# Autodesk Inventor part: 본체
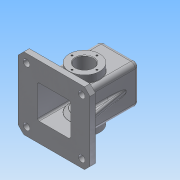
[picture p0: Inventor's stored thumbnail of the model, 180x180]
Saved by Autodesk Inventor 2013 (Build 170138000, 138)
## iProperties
Created: 2016-02
Part Number: 본체
Material: 알루미늄 6061
Document SubType Name: Modeling
Designer: Administrator
Density: 2.71 g/cm^3
Mass: 889.78 g
Surface Area: 1017.18 cm^2
Volume: 328.332 cm^3
Author: Administrator
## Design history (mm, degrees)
sketch "스케치1"
  geometry: L1 (65, 65)-(-65, 65); L2 (-65, 65)-(-65, -65); L3 (-65, -65)-(65, -65); L4 (65, -65)-(65, 65); L5 (65, 65)-(-65, -65); L6 (-65, 65)-(65, -65); 1 further point
  constraints: 12 end point, 2 midpoint, 2 parallel, 1 horizontal, 1 perpendicular
  dimensions: "d0" = 130 distance of L3.end L2.end; "d1" = 130 distance of L2.end L1.end
extrude "돌출1" new body sketch "스케치1" distance "d2" = 10; taper "d3" = 0 deg
sketch "스케치2"
  geometry: L1 (-35, -35)-(35, -35); L2 (35, -35)-(35, 35); L3 (35, 35)-(-35, 35); L4 (-35, 35)-(-35, -35); L5 (-35, -35)-(35, 35); L6 (35, -35)-(-35, 35); 1 further point
  constraints: 12 end point, 2 midpoint, 2 parallel, 1 horizontal, 1 perpendicular
  dimensions: "d4" = 70 distance of L3.end L2.end; "d5" = 70 distance of L2.end L1.end
extrude "돌출2" join sketch "스케치2" distance "d6" = 110; taper "d7" = 0 deg
sketch "스케치3"
  geometry: L1 (-35, -35)-(-35, 35) reference; L2 (-35, 35)-(35, 35) reference; L3 (35, 35)-(35, -35) reference; L4 (35, -35)-(-35, -35) reference; L5 (-65, -65)-(65, -65) reference; L6 (65, -65)-(65, 65) reference; L7 (65, 65)-(-65, 65) reference; L8 (-65, 65)-(-65, -65) reference; C1 r 20 at (0, 0); 1 further point
  constraints: 1 centre point, 1 coincident
  dimensions: "d8" = 40 diameter of C1
extrude "돌출3" join sketch "스케치3" distance "d9" = 10; taper "d10" = -10 deg
sketch "스케치4"
  geometry: L1 (0, 65)-(10, 65) reference; L2 (10, 65)-(10, 35) reference; L3 (10, 35)-(120, 35) reference; L4 (120, 35)-(120, 20) reference; L5 (120, 20)-(130, 18.237) reference; L6 (130, 18.237)-(130, -18.237) reference; L7 (130, -18.237)-(120, -20) reference; L8 (120, -20)-(120, -35) reference; L9 (120, -35)-(10, -35) reference; L10 (10, -35)-(10, -65) reference; L11 (10, -65)-(0, -65) reference; L12 (0, -65)-(0, 65) reference; L13 (115, 30)-(115, -30); L14 (115, -30)-(0, -30); L15 (115, 30)-(0, 30); 1 further point
  constraints: 6 end point, 2 parallel, 2 point on line, 1 perpendicular
  dimensions: "d11" = 5 distance between parallel lines of L3 L15; "d12" = 5 distance between parallel lines of L4 L13; "d13" = 5 distance between parallel lines of L9 L14
extrude "돌출4" cut sketch "스케치4" stored distance "d14" = 60; taper "d15" = 0 deg
chamfer "모따기1" distance "d16" = 10; stored, may be unused: second distance "d17" = 2, angle "d18" = 45 deg
sketch "스케치6"
  geometry: L1 (60, 0)-(0, 0) reference; L2 (-5, 10)-(-5, 120) reference; L3 (-5, 120)-(65, 120) reference; L4 (65, 120)-(65, 10) reference; L5 (65, 10)-(95, 10) reference; L6 (95, 10)-(95, 0) reference; L7 (95, 0)-(60, 0) reference; L8 (60, 0)-(0, 0) reference; L9 (0, 0)-(-35, 0) reference; L10 (-35, 0)-(-35, 10) reference; L11 (-35, 10)-(-5, 10) reference; L12 (60, 0)-(60, 115) reference; L13 (60, 115)-(0, 115) reference; L14 (0, 115)-(0, 0) reference; C1 r 27.5 at (30, 55); 2 further points
  constraints: 1 centre point, 1 midpoint, 1 vertical alignment
  dimensions: "d20" = 55 diameter of C1; "d21" = 55 distance from line of L1 C1.centre
extrude "돌출5" join sketch "스케치6" distance "d22" = 7; taper "d23" = -45 deg
sketch "스케치7"
  geometry: L1 (0, 110)-(70, 110) reference; L2 (-20, -10)-(90, -10) reference; C1 r 27.5 at (35, 45); 2 further points
  constraints: 1 centre point, 1 midpoint, 1 vertical alignment
  dimensions: "d24" = 55 diameter of C1; "d25" = 55 distance from line of L2 C1.centre
extrude "돌출6" join sketch "스케치7" distance "d26" = 13; taper "d27" = 0 deg
sketch "스케치8"
  geometry: C1 r 27.5 at (0, 0) reference; C2 r 16 at (0, 0); 1 further point
  constraints: 1 centre point, 1 coincident
  dimensions: "d28" = 32 diameter of C2
extrude "돌출7" cut sketch "스케치8" stored distance "d29" = 8; taper "d30" = 0 deg
sketch "스케치9"
  geometry: C1 r 18.237 at (0, 0) reference; 1 further point
  constraints: 1 coincident
hole "구멍1" sketch "스케치9" at (0, 0) diameter "d31" = 21; stored, may be unused: countersink angle "d35" = 90 deg, drill point angle "d37" = 118 deg; dims "d32" = 6, "d33" = 28, "d34" = 4, "d36" = 8
sketch "스케치10"
  geometry: L1 (-35, 10)-(-35, 120) reference; L2 (-35, 120)-(-20, 120) reference; L3 (-20, 120)-(-18.237, 130) reference; L4 (-18.237, 130)-(-14, 130) reference; L5 (-14, 130)-(-14, 126) reference; L6 (-14, 126)-(-10.5, 126) reference; L7 (-10.5, 126)-(-10.5, 115) reference; L8 (-10.5, 115)-(-30, 115) reference; L9 (-30, 115)-(-30, 0) reference; L10 (-30, 0)-(-65, 0) reference; L11 (-65, 0)-(-65, 10) reference; L12 (-65, 10)-(-35, 10) reference; L13 (35, 120)-(35, 10) reference; L14 (35, 10)-(65, 10) reference; L15 (65, 10)-(65, 0) reference; L16 (65, 0)-(30, 0) reference; L17 (30, 0)-(30, 115) reference; L18 (30, 115)-(10.5, 115) reference; L19 (10.5, 115)-(10.5, 126) reference; L20 (10.5, 126)-(14, 126) reference; L21 (14, 126)-(14, 130) reference; L22 (14, 130)-(18.237, 130) reference; L23 (18.237, 130)-(20, 120) reference; L24 (20, 120)-(35, 120) reference; L25 (35, 95.069)-(50, 10); 1 further point
  constraints: 2 end point, 1 midpoint, 1 point on line
  dimensions: "d40" = 10 deg angle of L15 L25; "d41" = 15 distance from line of L15 L25.end
feature "리브1" sketch "스케치10" dims "d42" = 1, "d43" = 10, "d44" = 0, "d45" = 0, "d46" = 1, "d47" = 1
sketch "스케치11"
  geometry: L1 (0, 0)-(0, 22.5); C1 r 27.5 at (0, 0) reference; 2 further points
  constraints: 2 end point, 1 coincident, 1 vertical
  dimensions: "d48" = 22.5 distance of L1.start L1.end
hole "구멍2" sketch "스케치11" at (0, 22.5) diameter "d49" = 3.242; stored, may be unused: countersink angle "d53" = 90 deg, drill point angle "d55" = 118 deg; dims "d50" = 8, "d51" = 28, "d52" = 4, "d54" = 10
fillet "모깎기1" dims "d59" = 8
fillet "모깎기2" dims "d60" = 0.5
fillet "모깎기3" dims "d61" = 8
fillet "모깎기4" dims "d62" = 3
fillet "모깎기5" dims "d63" = 3
fillet "모깎기6" dims "d64" = 3
fillet "모깎기7" dims "d65" = 3
fillet "모깎기8" dims "d66" = 0.5
chamfer "모따기2" distance "d67" = 1; stored, may be unused: second distance "d68" = 2, angle "d69" = 45 deg
sketch "스케치12"
  geometry: L1 (65, -55)-(65, 55) reference; L2 (55, 65)-(-55, 65) reference; L3 (-27, -30)-(27, -30) reference; L4 (30, -27)-(30, 27) reference; L5 (27, 30)-(-27, 30) reference; L6 (-30, 27)-(-30, -27) reference; L7 (38, -27)-(38, -8) reference; L8 (38, -8)-(46.425, -8) reference; L9 (52.517, -2)-(52.517, 2) reference; L10 (46.425, 8)-(38, 8) reference; L11 (38, 8)-(38, 27) reference; L12 (27, 38)-(-27, 38) reference; L13 (-38, 27)-(-38, 8) reference; L14 (-38, 8)-(-46.425, 8) reference; L15 (-52.517, 2)-(-52.517, -2) reference; L16 (-46.425, -8)-(-38, -8) reference; L17 (-38, -8)-(-38, -27) reference; L18 (-27, -38)-(27, -38) reference; L19 (55, 65)-(65, 55) reference; L20 (65, 55)-(65, -55) reference; L21 (65, -55)-(55, -65) reference; L22 (55, -65)-(-55, -65) reference; L23 (-55, -65)-(-65, -55) reference; L24 (-65, -55)-(-65, 55) reference; L25 (-65, 55)-(-55, 65) reference; L26 (-55, 65)-(55, 65) reference; A1 r 3 centre (27, -27) between (27, -30) and (30, -27) reference; A2 r 3 centre (27, 27) between (30, 27) and (27, 30) reference; A3 r 3 centre (-27, 27) between (-27, 30) and (-30, 27) reference; A4 r 3 centre (-27, -27) between (-30, -27) and (-27, -30) reference; A5 r 11 centre (27, -27) between (27, -38) and (38, -27) reference; A6 r 11 centre (27, 27) between (38, 27) and (27, 38) reference; A7 r 11 centre (-27, 27) between (-27, 38) and (-38, 27) reference; A8 r 11 centre (-27, -27) between (-38, -27) and (-27, -38) reference; 5 further points
  constraints: 2 horizontal alignment, 2 vertical alignment, 4 other
  dimensions: "d70" = 100 distance of point (-50, -50) point (-50, 50); "d72" = 100 distance of point (50, 50) point (-50, 50); "d73" = 15 distance from line of L1 point (50, 50); "d74" = 15 distance from line of L2 point (50, 50)
hole "구멍3" sketch "스케치12" at (-50, 50), (50, 50), (50, -50), (-50, -50) diameter "d75" = 12; stored, may be unused: countersink angle "d79" = 90 deg, drill point angle "d81" = 118 deg; dims "d76" = 8, "d77" = 28, "d78" = 4, "d80" = 10
sketch "스케치13"
  geometry: L1 (-18.237, 75)-(18.237, 75) reference; A1 r 28 centre (0, 0) between (27, 7.416) and (-27, 7.416) reference; 2 further points
  constraints: 1 vertical alignment, 1 other
  dimensions: "d82" = 30 distance from line of point (0, 45) L1
feature "엠보싱1" sketch "스케치13" dims "d0" = 130, "d1" = 130, "d83" = 0.5, "d84" = 0
node "솔리드1"
mirror "대칭1"
mirror "대칭2"
pattern_circular "원형 패턴1" dims angle "d57" = 360 deg
mirror "대칭3"
node "투영된 루프1"
node "절단 모서리 투영1"
node "절단 모서리 투영3"
node "절단 모서리 투영4"
node "절단 모서리 투영5"
